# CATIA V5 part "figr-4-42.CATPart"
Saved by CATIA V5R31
Part number: Part1
Bounding box of the stored display mesh (mm): x -59.931 to 60.019, y -73.049 to 76.86, z -59.931 to 60.019
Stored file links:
  D:\PROJECTS\Project 2021\US EDITION\CATIA V5 6R 2021\Resources\Part Files\c04_catia_v5_6r2020_prt\figr-4-42.CATPart
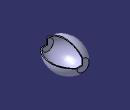
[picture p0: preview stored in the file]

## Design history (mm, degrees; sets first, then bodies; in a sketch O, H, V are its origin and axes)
Body1 (main body)
  Sketch1 on yz-plane, origin (0, 0, 0), H (0, 1, 0), V (0, 0, 1)
    point P1 (76.8601, 0)
    line L1 (76.8601, 0) -> (76.8601, 25)
    construction line L2 through (0, 0) direction (-1, 0)
    point P5 (-73.049, 0)
    line L3 (-73.049, 0) -> (-73.049, 25)
    axis line L4 (-100, 0) -> (100, 0)
    arc A1 centre (1.9056, -37.7079) radius 97.7265 from (76.8601, 25) to (-73.049, 25) ccw
    point P10 (0, 60)
    length L1 = 25
    length L3 = 25
    horizontal: L4 H
    vertical: L3 V, L1 V
    coincidence: P1 L4, L4 L2, P5 L4, L4 H, A1 P10, P10 V
  Shaft1: profile Sketch1, axis Sketch1.L4, angle 270, thin wall 4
